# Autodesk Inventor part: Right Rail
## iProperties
Shininess: 64.0
Length Units: 11272
Angle Units: 11279
Time Units: 11290
Mass Units: 11286
Length Display Precision: 3
Angle Display Precision: 2
Compacted: True
Part Number: Right Rail
Document SubType Name: Modeling
Created: 2003-10
Designer: jpittman
Manufacturer: Standard
Standards Organization: Custom
Density: 0.0
Volumn: 0.0
Area: 0.0
PropertySet Name: Model Information
Control State: 0
Master: False
Checked Out: False
Author: jpittman
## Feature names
1. Extrusion1
2. Extrusion3
3. Extrusion4
4. Hole2
5. Hole3
